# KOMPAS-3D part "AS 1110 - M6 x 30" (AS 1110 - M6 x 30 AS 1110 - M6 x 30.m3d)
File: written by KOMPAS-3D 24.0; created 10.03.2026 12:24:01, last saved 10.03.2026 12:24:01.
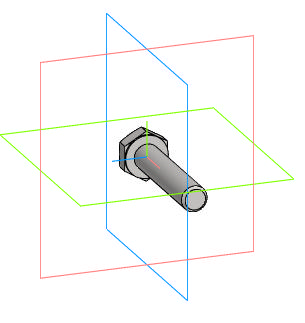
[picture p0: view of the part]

Document properties: Автор: R2D2; Полное имя файла: E:\Работа\Зайцев\BV3232P(4pc)-FP-3WL-F-ISO-H Кран шаровой DN.ru Ду15-100 Ру16\DN32\исходные материалы\AS 1110 - M6 x 30 AS 1110 - M6 x 30.m3d

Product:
- Body: Solid1  | qty 1
- Part/product: AS 1110 - M6 x 30
    Комментарий: Болты и винты   шестигранные точные   метрические ISO
    additional columns: Сталь, мягкая

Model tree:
1. Solid1  (labels: Solid1)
